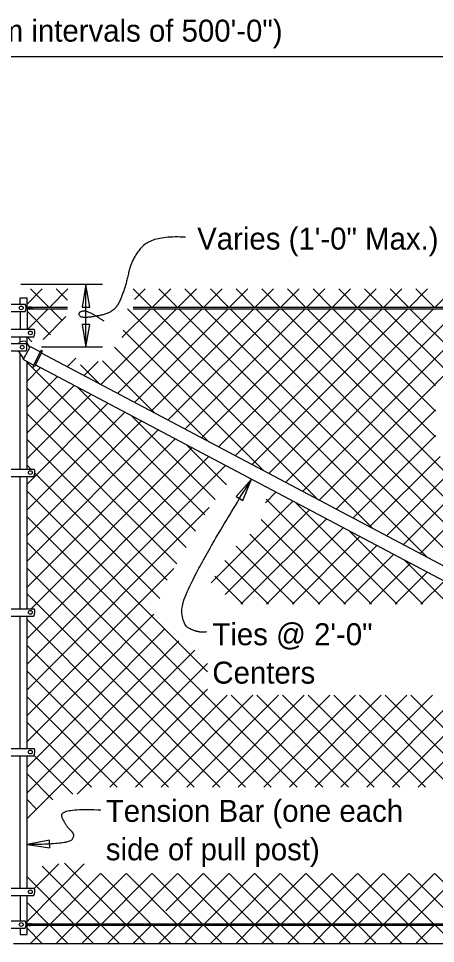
# Model space of a CAD drawing. Extents: x 0.5 to 39.7, y 0.9 to 25.6.
# Drawn here: x 12.4 to 16.23, y 17.14 to 25.61 of the extents above; entities that cross this region are included whole.
import ezdxf

# ---------------------------------------------------------------- set-up
doc = ezdxf.new("R2010")
doc.units = 0
for name, color, linetype in [('Dimension', 7, 'Continuous'), ('Miscellaneous', 7, 'Continuous'), ('SteelMisc', 7, 'Continuous'), ('SupstrConc', 7, 'Continuous'), ('TextStructures', 7, 'Continuous')]:
    doc.layers.add(name, color=color, linetype=linetype)

msp = doc.modelspace()

# ---------------------------------------------------------------- linework, layer by layer
at = {"layer": 'Dimension'}
for p, q in [((2.2062, 25.2672), (22.2062, 25.2672)), ((13.1684, 23.1761), (12.4194, 23.1761)), ((13.0184, 22.6012), (13.0184, 23.1761)), ((13.1684, 22.6012), (12.6093, 22.6012))]:
    msp.add_line(p, q, dxfattribs=at)
for points in [[(13.0184, 23.1761), (12.9832, 22.9678), (13.0537, 22.9678)], [(13.0184, 22.6012), (13.0537, 22.8095), (12.9832, 22.8095)], [(14.5361, 21.3922), (14.3971, 21.2332), (14.4572, 21.1963)], [(12.4771, 18.0429), (12.6863, 18.0139), (12.6842, 18.0844)]]:
    msp.add_lwpolyline(points, close=True, dxfattribs=at)
for points in [[(13.9321, 23.6099), (13.634, 23.6259), (13.4393, 23.4234), (13.3796, 23.1471), (13.2873, 22.9252), (13.0658, 22.8744), (12.9551, 22.8744), (12.9551, 22.9344), (13.0474, 22.9344), (13.1812, 22.842)], [(14.1244, 19.9926), (14.0777, 19.9785), (13.8948, 20.0458), (13.9033, 20.3724), (14.5362, 21.3922)], [(13.1545, 18.3586), (12.7557, 18.3765), (12.8361, 18.2097), (12.9224, 18.1322), (12.8539, 18.0428), (12.4771, 18.0428)]]:
    msp.add_open_spline(points, degree=2, dxfattribs=at)
at = {"layer": 'Miscellaneous'}
for p, q in [((12.4771, 22.996), (12.6172, 23.1361)), ((12.5097, 23.1361), (12.6764, 22.9695)), ((12.6862, 22.9695), (12.8529, 23.1361)), ((12.7454, 23.1361), (12.8477, 23.0339)), ((13.4525, 23.1361), (13.6192, 22.9695)), ((13.463, 23.0391), (13.56, 23.1361)), ((13.629, 22.9695), (13.7957, 23.1361)), ((13.6882, 23.1361), (13.8549, 22.9695)), ((13.8647, 22.9695), (14.0314, 23.1361)), ((13.9239, 23.1361), (14.0906, 22.9695)), ((14.1004, 22.9695), (14.2671, 23.1361)), ((14.1597, 23.1361), (14.3263, 22.9695)), ((14.3361, 22.9695), (14.5028, 23.1361)), ((14.3954, 23.1361), (14.562, 22.9695)), ((14.5718, 22.9695), (14.7385, 23.1361)), ((14.6311, 23.1361), (14.7977, 22.9695)), ((14.8075, 22.9695), (14.9742, 23.1361)), ((14.8668, 23.1361), (15.0334, 22.9695)), ((15.0432, 22.9695), (15.2099, 23.1361)), ((15.1025, 23.1361), (15.2691, 22.9695)), ((15.2789, 22.9695), (15.4456, 23.1361)), ((15.3382, 23.1361), (15.5048, 22.9695)), ((15.5146, 22.9695), (15.6813, 23.1361)), ((15.5739, 23.1361), (15.7405, 22.9695)), ((15.7503, 22.9695), (15.917, 23.1361)), ((15.8096, 23.1361), (15.9762, 22.9695)), ((15.986, 22.9695), (16.1527, 23.1361)), ((16.0453, 23.1361), (16.2119, 22.9695)), ((16.2217, 22.9695), (16.3884, 23.1361)), ((12.4771, 22.9331), (12.6938, 22.7164)), ((12.4821, 22.7653), (12.6715, 22.9547)), ((12.6912, 22.9547), (12.7998, 22.8461)), ((13.1537, 22.2584), (13.85, 22.9547)), ((13.3079, 22.177), (14.0857, 22.9547)), ((13.3487, 22.6891), (13.6143, 22.9547)), ((13.3983, 22.9547), (15.1489, 21.2041)), ((13.4621, 22.0955), (14.3214, 22.9547)), ((13.6163, 22.014), (14.5571, 22.9547)), ((13.634, 22.9547), (15.6487, 20.94)), ((13.7706, 21.9325), (14.7928, 22.9547)), ((13.8697, 22.9547), (16.1486, 20.6758)), ((13.9248, 21.851), (15.0285, 22.9547)), ((14.079, 21.7695), (15.2642, 22.9547)), ((14.1054, 22.9547), (16.6484, 20.4117)), ((14.2332, 21.688), (15.4999, 22.9547)), ((14.3411, 22.9547), (17.1483, 20.1475)), ((14.3874, 21.6065), (15.7356, 22.9547)), ((14.5416, 21.525), (15.9713, 22.9547)), ((14.5768, 22.9547), (17.4573, 20.0742)), ((14.6958, 21.4435), (16.207, 22.9547)), ((14.8125, 22.9547), (17.4573, 20.3099)), ((14.85, 21.362), (16.4427, 22.9547)), ((15.0042, 21.2805), (16.6784, 22.9547)), ((15.0482, 22.9547), (16.224, 21.7789)), ((15.1584, 21.199), (16.9141, 22.9547)), ((15.2839, 22.9547), (16.224, 22.0146)), ((15.5196, 22.9547), (16.224, 22.2503)), ((15.7553, 22.9547), (16.393, 22.317)), ((15.991, 22.9547), (16.6287, 22.317)), ((12.625, 22.6726), (12.8347, 22.8823)), ((13.3596, 22.7577), (14.649, 21.4683)), ((12.4771, 22.6974), (12.5225, 22.6519)), ((13.2788, 22.6027), (14.1492, 21.7324)), ((12.8453, 22.4214), (12.9257, 22.5019)), ((12.9995, 22.3399), (13.1301, 22.4705)), ((13.1699, 22.476), (13.6493, 21.9966)), ((12.4771, 22.4617), (14.0233, 20.9155)), ((12.4771, 22.2889), (12.6023, 22.4142)), ((12.9688, 22.4413), (13.1494, 22.2607)), ((12.4771, 22.0532), (12.7565, 22.3327)), ((12.4771, 21.8175), (12.9108, 22.2512)), ((12.4771, 22.226), (13.9369, 20.7661)), ((12.9373, 22.2372), (14.1096, 21.0648)), ((12.4771, 21.5818), (13.065, 22.1697)), ((12.4771, 21.3461), (13.2192, 22.0882)), ((12.4771, 21.9903), (13.8506, 20.6168)), ((12.4835, 21.1168), (13.3734, 22.0067)), ((13.4371, 21.973), (14.2041, 21.206)), ((15.3127, 21.1175), (16.224, 22.0289)), ((12.4771, 20.8747), (13.5276, 21.9252)), ((12.4771, 20.639), (13.6818, 21.8437)), ((15.4669, 21.0361), (16.224, 21.7932)), ((12.4771, 20.4033), (13.836, 21.7622)), ((12.4771, 21.7546), (13.7642, 20.4674)), ((13.937, 21.7089), (14.3067, 21.3392)), ((12.5138, 20.2043), (13.9902, 21.6807)), ((12.4771, 19.9319), (14.1444, 21.5993)), ((14.5173, 21.6), (14.649, 21.4683)), ((15.6211, 20.9546), (16.2665, 21.6)), ((15.7753, 20.8731), (16.5022, 21.6)), ((15.7753, 20.8731), (16.5022, 21.6)), ((15.9295, 20.7916), (16.7379, 21.6)), ((15.9295, 20.7916), (16.7379, 21.6)), ((16.0837, 20.7101), (16.9736, 21.6)), ((16.0837, 20.7101), (16.9736, 21.6)), ((12.4771, 21.5189), (12.5111, 21.4848)), ((12.4771, 19.6962), (14.2987, 21.5178)), ((12.5494, 21.4465), (13.6969, 20.2991)), ((12.4771, 21.2832), (14.1345, 19.6257)), ((14.6643, 21.1763), (14.7613, 21.2733)), ((14.6726, 21.2089), (15.6365, 20.2451)), ((12.4771, 19.4605), (14.1483, 21.1317)), ((14.1658, 20.4421), (14.9155, 21.1918)), ((14.9366, 21.1806), (15.8722, 20.2451)), ((12.4771, 21.0475), (14.9544, 18.5701)), ((14.2953, 20.3359), (15.0697, 21.1103)), ((14.4402, 20.2451), (15.2239, 21.0288)), ((14.6248, 21.0211), (15.4008, 20.2451)), ((14.6759, 20.2451), (15.3781, 20.9473)), ((14.5225, 20.8877), (15.1651, 20.2451)), ((14.9116, 20.2451), (15.5323, 20.8658)), ((15.4365, 20.9165), (16.1079, 20.2451)), ((12.4771, 20.8118), (14.7187, 18.5701)), ((14.3976, 20.7769), (14.9294, 20.2451)), ((15.1473, 20.2451), (15.6866, 20.7843)), ((15.383, 20.2451), (15.8408, 20.7028)), ((14.2931, 20.6457), (14.6937, 20.2451)), ((15.6187, 20.2451), (15.995, 20.6214)), ((15.9363, 20.6524), (19.2711, 17.3175)), ((12.4771, 20.5761), (14.483, 18.5701)), ((12.4771, 19.2248), (13.8252, 20.5729)), ((15.8544, 20.2451), (16.1492, 20.5399)), ((14.1993, 20.5038), (14.458, 20.2451)), ((16.0901, 20.2451), (16.3034, 20.4584)), ((12.4771, 20.3404), (14.2473, 18.5701)), ((12.4771, 18.9891), (13.6423, 20.1543)), ((12.4771, 20.1047), (14.0116, 18.5701)), ((12.4771, 18.7534), (13.737, 20.0133)), ((15.5936, 18.5701), (17.0744, 20.0509)), ((15.8293, 18.5701), (17.2287, 19.9694)), ((12.4771, 18.5177), (13.8698, 19.9104)), ((12.4771, 19.869), (13.7759, 18.5701)), ((16.065, 18.5701), (17.3829, 19.8879)), ((12.4771, 18.282), (14.0185, 19.8234)), ((12.9361, 18.5053), (14.1345, 19.7037)), ((12.4771, 19.6333), (13.5402, 18.5701)), ((13.2366, 18.5701), (14.1345, 19.468)), ((12.4771, 19.3976), (13.3045, 18.5701)), ((13.4723, 18.5701), (14.3131, 19.4109)), ((13.708, 18.5701), (14.5488, 19.4109)), ((13.9437, 18.5701), (14.7845, 19.4109)), ((14.1794, 18.5701), (15.0202, 19.4109)), ((14.3493, 19.4109), (15.1901, 18.5701)), ((14.4151, 18.5701), (15.2559, 19.4109)), ((14.585, 19.4109), (15.4258, 18.5701)), ((14.6508, 18.5701), (15.4916, 19.4109)), ((14.8207, 19.4109), (15.6615, 18.5701)), ((14.8865, 18.5701), (15.7274, 19.4109)), ((15.0564, 19.4109), (15.8972, 18.5701)), ((15.1222, 18.5701), (15.9631, 19.4109)), ((15.2921, 19.4109), (16.1329, 18.5701)), ((15.3579, 18.5701), (16.1988, 19.4109)), ((15.5278, 19.4109), (16.3686, 18.5701)), ((15.7635, 19.4109), (17.8569, 17.3175)), ((15.9992, 19.4109), (18.0926, 17.3175)), ((12.4771, 19.1619), (13.0688, 18.5701)), ((12.5429, 18.8603), (12.897, 18.5062)), ((12.4771, 18.6905), (12.715, 18.4525)), ((12.4771, 18.4548), (12.5674, 18.3644)), ((12.4771, 17.3391), (13.0028, 17.8649)), ((12.5428, 17.6406), (12.7683, 17.8661)), ((12.6161, 17.8443), (13.1429, 17.3175)), ((12.8223, 17.8738), (13.3786, 17.3175)), ((12.4771, 17.7476), (12.9072, 17.3175)), ((12.6912, 17.3175), (13.1513, 17.7777)), ((12.9269, 17.3175), (13.387, 17.7777)), ((13.1541, 17.7777), (13.6143, 17.3175)), ((13.1626, 17.3175), (13.6227, 17.7777)), ((13.3898, 17.7777), (13.85, 17.3175)), ((13.3983, 17.3175), (13.8584, 17.7777)), ((13.6255, 17.7777), (14.0857, 17.3175)), ((13.7518, 17.4354), (14.0941, 17.7777)), ((13.8612, 17.7777), (14.3214, 17.3175)), ((13.8697, 17.3175), (14.3298, 17.7777)), ((14.0969, 17.7777), (14.5571, 17.3175)), ((14.1054, 17.3175), (14.5655, 17.7777)), ((14.3326, 17.7777), (14.7928, 17.3175)), ((14.3411, 17.3175), (14.8012, 17.7777)), ((14.5683, 17.7777), (15.0285, 17.3175)), ((14.5768, 17.3175), (15.0369, 17.7777)), ((14.804, 17.7777), (15.2642, 17.3175)), ((14.8125, 17.3175), (15.2726, 17.7777)), ((15.0397, 17.7777), (15.4999, 17.3175)), ((15.0482, 17.3175), (15.5083, 17.7777)), ((15.2754, 17.7777), (15.7356, 17.3175)), ((15.2839, 17.3175), (15.744, 17.7777)), ((15.5111, 17.7777), (15.9713, 17.3175)), ((15.5196, 17.3175), (15.9797, 17.7777)), ((15.7468, 17.7777), (16.207, 17.3175)), ((15.7553, 17.3175), (16.2155, 17.7777)), ((15.9825, 17.7777), (16.4427, 17.3175)), ((15.991, 17.3175), (16.4503, 17.7768)), ((16.2182, 17.7777), (16.6784, 17.3175)), ((12.4771, 17.5119), (12.6715, 17.3175)), ((12.5097, 17.1361), (12.6764, 17.3028)), ((12.6862, 17.3028), (12.8529, 17.1361)), ((12.7454, 17.1361), (12.9121, 17.3028)), ((12.9219, 17.3028), (13.0886, 17.1361)), ((12.9811, 17.1361), (13.1478, 17.3028)), ((13.1576, 17.3028), (13.3243, 17.1361)), ((13.2168, 17.1361), (13.3835, 17.3028)), ((13.3933, 17.3028), (13.56, 17.1361)), ((13.4525, 17.1361), (13.6192, 17.3028)), ((13.629, 17.3028), (13.7957, 17.1361)), ((13.6882, 17.1361), (13.8549, 17.3028)), ((13.8647, 17.3028), (14.0314, 17.1361)), ((13.9239, 17.1361), (14.0906, 17.3028)), ((14.1004, 17.3028), (14.2671, 17.1361)), ((14.1597, 17.1361), (14.3263, 17.3028)), ((14.3361, 17.3028), (14.5028, 17.1361)), ((14.3954, 17.1361), (14.562, 17.3028)), ((14.5718, 17.3028), (14.7385, 17.1361)), ((14.6311, 17.1361), (14.7977, 17.3028)), ((14.8075, 17.3028), (14.9742, 17.1361)), ((14.8668, 17.1361), (15.0334, 17.3028)), ((15.0432, 17.3028), (15.2099, 17.1361)), ((15.1025, 17.1361), (15.2691, 17.3028)), ((15.2789, 17.3028), (15.4456, 17.1361)), ((15.3382, 17.1361), (15.5048, 17.3028)), ((15.5146, 17.3028), (15.6813, 17.1361)), ((15.5739, 17.1361), (15.7405, 17.3028)), ((15.7503, 17.3028), (15.917, 17.1361)), ((15.8096, 17.1361), (15.9762, 17.3028)), ((15.986, 17.3028), (16.1527, 17.1361)), ((16.0453, 17.1361), (16.2119, 17.3028)), ((16.2217, 17.3028), (16.3884, 17.1361)), ((12.4771, 17.2762), (12.6172, 17.1361))]:
    msp.add_line(p, q, dxfattribs=at)
at = {"layer": 'SteelMisc'}
for p, q in [((12.0505, 22.9966), (12.4602, 22.9966)), ((12.4146, 22.9966), (12.4146, 23.0528)), ((12.4146, 23.0528), (12.4771, 23.0528)), ((12.4146, 22.9966), (12.4146, 23.0528)), ((12.4146, 23.0528), (12.4771, 23.0528)), ((12.4771, 22.9726), (12.4771, 23.0528)), ((12.4771, 22.9726), (12.4771, 23.0528)), ((12.0505, 22.9289), (12.4599, 22.9289)), ((12.4146, 22.9288), (12.4146, 22.7653)), ((12.4146, 22.9288), (12.4146, 22.7653)), ((12.4675, 22.9741), (12.4968, 22.9695)), ((12.4676, 22.9741), (12.4969, 22.9695)), ((12.468, 22.9537), (12.5017, 22.9593)), ((12.4681, 22.9691), (12.4942, 22.965)), ((12.4681, 22.9537), (12.5018, 22.9593)), ((12.4682, 22.9691), (12.4943, 22.965)), ((12.4684, 22.9585), (12.4983, 22.9634)), ((12.4685, 22.9585), (12.4984, 22.9634)), ((12.4771, 22.9676), (12.4771, 22.9598)), ((12.4771, 22.9676), (12.4771, 22.9598)), ((12.4771, 22.9552), (12.4771, 22.7653)), ((12.4771, 22.9552), (12.4771, 22.7653)), ((12.4881, 22.9547), (12.8472, 22.9547)), ((12.4894, 22.9695), (12.8472, 22.9695)), ((13.4503, 22.9695), (21.8852, 22.9695)), ((13.4503, 22.9547), (21.9119, 22.9547)), ((12.0505, 22.7654), (12.5416, 22.7654)), ((12.0505, 22.6977), (12.5408, 22.6977)), ((12.4146, 22.6487), (12.4146, 22.6977)), ((12.5028, 22.6018), (12.468, 22.6549)), ((12.4771, 22.6411), (12.4771, 22.6977)), ((11.9439, 22.6358), (12.4686, 22.6358)), ((11.9439, 22.568), (12.4686, 22.568)), ((12.4467, 22.4958), (12.3998, 22.5675)), ((12.5062, 22.6083), (12.4425, 22.4877)), ((12.5062, 22.6083), (12.6005, 22.5585)), ((12.6051, 22.5671), (12.5327, 22.43)), ((12.617, 22.5609), (12.5445, 22.4237)), ((12.4146, 21.4848), (12.4146, 22.545)), ((12.5368, 22.4379), (12.4425, 22.4877)), ((12.4771, 21.4848), (12.4771, 22.4695)), ((21.8588, 17.6582), (12.6092, 22.5462)), ((21.8029, 17.5522), (12.5532, 22.4401)), ((12.4146, 21.4848), (12.4146, 22.0501)), ((12.4771, 21.4848), (12.4771, 22.0155)), ((12.0505, 21.4848), (12.5416, 21.4848)), ((12.0505, 21.4172), (12.5408, 21.4172)), ((12.4146, 20.2043), (12.4146, 21.4172)), ((12.4771, 20.2043), (12.4771, 21.4172)), ((12.0505, 20.2043), (12.5416, 20.2043)), ((12.0505, 20.1367), (12.5408, 20.1367)), ((12.4146, 18.9238), (12.4146, 20.1367)), ((12.4771, 18.9238), (12.4771, 20.1367)), ((12.0505, 18.9238), (12.5416, 18.9238)), ((12.0505, 18.8562), (12.5408, 18.8562)), ((12.4146, 17.6433), (12.4146, 18.8561)), ((12.4771, 17.6433), (12.4771, 18.8561)), ((12.0505, 17.6434), (12.5416, 17.6434)), ((12.0505, 17.5757), (12.5408, 17.5757)), ((12.4146, 17.5757), (12.4146, 17.3447)), ((12.4771, 17.3207), (12.4771, 17.5757)), ((11.9524, 17.3447), (12.4602, 17.3447)), ((12.4675, 17.3222), (12.4968, 17.3176)), ((12.4676, 17.3222), (12.4969, 17.3176)), ((12.468, 17.3018), (12.5017, 17.3074)), ((12.4681, 17.3171), (12.4942, 17.3131)), ((12.4681, 17.3018), (12.5018, 17.3074)), ((12.4682, 17.3171), (12.4943, 17.3131)), ((12.4684, 17.3065), (12.4983, 17.3115)), ((12.4685, 17.3065), (12.4984, 17.3115)), ((12.4771, 17.3079), (12.4771, 17.3157)), ((12.4771, 17.3079), (12.4771, 17.3157)), ((12.4771, 17.2195), (12.4771, 17.3032)), ((12.5141, 17.3028), (21.9119, 17.3028)), ((12.5154, 17.3175), (21.8852, 17.3175)), ((11.9526, 17.2769), (12.4599, 17.2769)), ((12.4146, 17.2769), (12.4146, 17.2195)), ((12.4146, 17.2195), (12.4771, 17.2195))]:
    msp.add_line(p, q, dxfattribs=at)
for centre, start, end in [((12.6109, 22.5639), 332.14902, 152.14902), ((12.5384, 22.4267), 152.14902, 332.14902)]:
    msp.add_arc(centre, 0.00673, start, end, dxfattribs=at)
for centre, major_axis in [((12.4242, 22.9621), (-0.0178, 0)), ((12.4242, 22.9621), (-0.0178, 0)), ((12.5079, 22.7326), (-0.0177, 0)), ((12.5079, 22.7326), (-0.0177, 0)), ((12.4327, 22.6012), (-0.0178, 0)), ((12.5079, 21.4521), (-0.0177, 0)), ((12.5079, 21.4521), (-0.0177, 0)), ((12.5079, 20.1716), (-0.0177, 0)), ((12.5079, 20.1716), (-0.0177, 0)), ((12.5079, 18.891), (-0.0177, 0)), ((12.5079, 18.891), (-0.0177, 0)), ((12.5079, 17.6106), (-0.0177, 0)), ((12.4242, 17.3102), (-0.0178, 0)), ((12.4242, 17.3102), (-0.0178, 0))]:
    msp.add_ellipse(centre, major_axis=major_axis, ratio=0.957868, dxfattribs=at)
for centre, major_axis, ratio, start_param, end_param in [((12.3909, 22.963), (0.0776, 0), 0.957868, 5.803915, 6.752041), ((12.3909, 22.963), (0.0776, 0), 0.957868, 5.803915, 6.752041), ((12.4993, 22.9596), (-0.0095, 0), 0.957868, 5.673972, 6.052579), ((12.4993, 22.9596), (-0.0095, 0), 0.957868, 5.673972, 6.052579), ((12.4993, 22.9596), (-0.0095, 0), 0.957868, 0.252467, 1.271421), ((12.4993, 22.9596), (-0.0095, 0), 0.957868, 0.252467, 1.271421), ((12.4953, 22.9604), (0.0115, -0.0041), 0.737732, 5.08821, 8.212701), ((12.4953, 22.9604), (0.0115, -0.0041), 0.737732, 5.08821, 8.212701), ((12.4934, 22.9555), (0.00982, 0), 0.957868, 0.655696, 1.505671), ((12.4934, 22.9555), (0.00982, 0), 0.957868, 0.655696, 1.505671), ((12.4988, 22.9579), (0.00301, 0), 0.957868, 3.28349, 5.170635), ((12.4988, 22.9579), (0.00301, 0), 0.957868, 3.28349, 5.170635), ((12.4994, 22.9601), (-0.00453, 0), 0.957868, 5.149727, 5.551998), ((12.4994, 22.9601), (-0.00453, 0), 0.957868, 5.149727, 5.551998), ((12.4966, 22.9588), (0.00527, 0), 0.957868, 5.058829, 7.342751), ((12.4966, 22.9588), (0.00527, 0), 0.957868, 5.058829, 7.342751), ((12.501, 22.9612), (-0.00872, 0), 0.957868, 2.1008, 4.992926), ((12.501, 22.9612), (-0.00872, 0), 0.957868, 2.1008, 4.992926), ((12.4988, 22.9579), (0.00301, 0), 0.957868, 0.004594, 0.141897), ((12.4988, 22.9579), (0.00301, 0), 0.957868, 0.004594, 0.141897), ((12.5071, 22.9608), (0.00944, 0), 0.957868, 4.316497, 6.557353), ((12.5071, 22.9608), (0.00944, 0), 0.957868, 4.316497, 6.557353), ((12.5076, 22.9617), (-0.00872, 0), 0.957868, 3.323334, 4.992926), ((12.5076, 22.9617), (-0.00872, 0), 0.957868, 3.323334, 4.992926), ((12.5076, 22.9617), (-0.00503, 0), 0.92697, 1.780895, 4.712389), ((12.5076, 22.9617), (-0.00503, 0), 0.92697, 1.780895, 4.712389), ((12.5123, 22.9562), (-0.0142, 0), 0.957868, 3.141593, 4.79635), ((12.5123, 22.9562), (-0.0142, 0), 0.957868, 3.141593, 4.79635), ((12.5043, 22.9412), (0.0274, 0), 0.957868, 0.628521, 1.149654), ((12.5043, 22.9412), (0.0274, 0), 0.957868, 0.628521, 1.149654), ((12.472, 22.7322), (0.0776, 0), 0.957868, 5.801244, 6.745158), ((12.472, 22.7322), (0.0776, 0), 0.957868, 5.801244, 6.745158), ((12.4514, 22.5866), (-0.0647, 0.0342), 0.957868, 4.95193, 6.011789), ((12.3994, 22.6016), (0.0776, 0), 0.957868, 5.810211, 6.75616), ((12.472, 21.4517), (0.0776, 0), 0.957868, 5.801046, 6.744962), ((12.472, 21.4517), (0.0776, 0), 0.957868, 5.801046, 6.744962), ((12.472, 20.1712), (0.0776, 0), 0.957868, 5.800848, 6.744767), ((12.472, 20.1712), (0.0776, 0), 0.957868, 5.800848, 6.744767), ((12.472, 18.8906), (0.0776, 0), 0.957868, 5.810211, 6.745158), ((12.472, 18.8906), (0.0776, 0), 0.957868, 5.810211, 6.745158), ((12.472, 17.6101), (0.0776, 0), 0.957868, 5.800651, 6.745353), ((12.3909, 17.311), (0.0776, 0), 0.957868, 5.803915, 6.752041), ((12.3909, 17.311), (0.0776, 0), 0.957868, 5.803915, 6.752041), ((12.4993, 17.3077), (-0.0095, 0), 0.957868, 5.673972, 6.052579), ((12.4993, 17.3077), (-0.0095, 0), 0.957868, 5.673972, 6.052579), ((12.4993, 17.3077), (-0.0095, 0), 0.957868, 0.252467, 1.271421), ((12.4993, 17.3077), (-0.0095, 0), 0.957868, 0.252467, 1.271421), ((12.4953, 17.3084), (0.0115, -0.0041), 0.737732, 5.08821, 8.212701), ((12.4953, 17.3084), (0.0115, -0.0041), 0.737732, 5.08821, 8.212701), ((12.4934, 17.3035), (0.00982, 0), 0.957868, 0.655696, 1.505671), ((12.4934, 17.3035), (0.00982, 0), 0.957868, 0.655696, 1.505671), ((12.4988, 17.306), (0.00301, 0), 0.957868, 3.28349, 5.170635), ((12.4988, 17.306), (0.00301, 0), 0.957868, 3.28349, 5.170635), ((12.4994, 17.3082), (-0.00453, 0), 0.957868, 5.149727, 5.551998), ((12.4994, 17.3082), (-0.00453, 0), 0.957868, 5.149727, 5.551998), ((12.4966, 17.3069), (0.00527, 0), 0.957868, 5.058829, 7.342751), ((12.4966, 17.3069), (0.00527, 0), 0.957868, 5.058829, 7.342751), ((12.501, 17.3093), (-0.00872, 0), 0.957868, 2.1008, 4.992926), ((12.501, 17.3093), (-0.00872, 0), 0.957868, 2.1008, 4.992926), ((12.4988, 17.306), (0.00301, 0), 0.957868, 0.004594, 0.141897), ((12.4988, 17.306), (0.00301, 0), 0.957868, 0.004594, 0.141897), ((12.5071, 17.3089), (0.00944, 0), 0.957868, 4.316497, 6.557353), ((12.5071, 17.3089), (0.00944, 0), 0.957868, 4.316497, 6.557353), ((12.5076, 17.3098), (-0.00872, 0), 0.957868, 3.323334, 4.992926), ((12.5076, 17.3098), (-0.00872, 0), 0.957868, 3.323334, 4.992926), ((12.5076, 17.3098), (-0.00503, 0), 0.92697, 1.780895, 4.712389), ((12.5076, 17.3098), (-0.00503, 0), 0.92697, 1.780895, 4.712389), ((12.5123, 17.3043), (-0.0142, 0), 0.957868, 3.141593, 4.79635), ((12.5123, 17.3043), (-0.0142, 0), 0.957868, 3.141593, 4.79635), ((12.5043, 17.2893), (0.0274, 0), 0.957868, 0.628521, 1.149654), ((12.5043, 17.2893), (0.0274, 0), 0.957868, 0.628521, 1.149654)]:
    msp.add_ellipse(centre, major_axis=major_axis, ratio=ratio, start_param=start_param, end_param=end_param, dxfattribs=at)
at = {"layer": 'SupstrConc'}
msp.add_line((12.3521, 17.1361), (18.8204, 17.1361), dxfattribs=at)

# ---------------------------------------------------------------- texts
at = {"layer": 'TextStructures'}
for s, p in [('Pull Post Assembly (required at maximum intervals of 500\'-0")', (7.4383, 25.402)), ('Varies (1\'-0" Max.)  (Typ.)', (14.0385, 23.4963)), ('Ties @ 2\'-0" ', (14.1779, 19.8699)), ('Centers', (14.1779, 19.5179)), ('Tension Bar (one each ', (13.2005, 18.2509)), ('side of pull post)', (13.2005, 17.8989))]:
    msp.add_text(s, height=0.2016, dxfattribs=at).set_placement(p)

doc.saveas('drawing.dxf')
